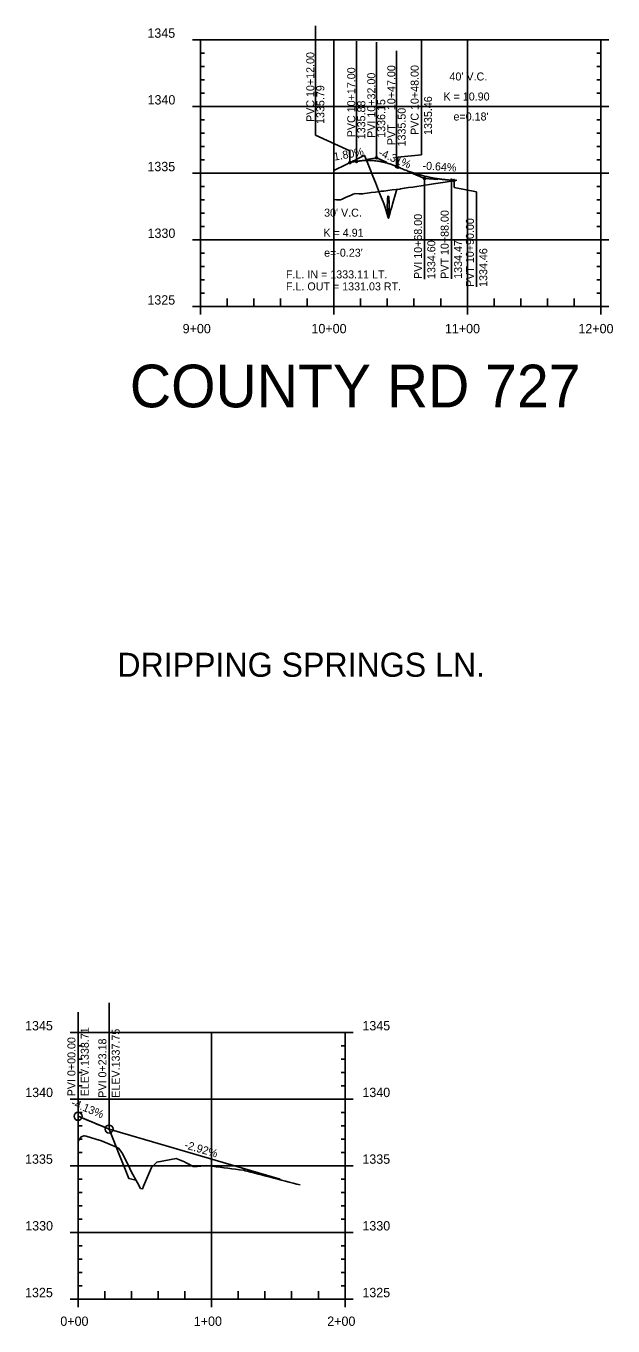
# Model space of a CAD drawing. Extents: x 1371206 to 1374178, y 379328 to 381511.
# Drawn here: x 1372543 to 1372983, y 380536 to 381511 of the extents above; entities that cross this region are included whole.
import ezdxf

# ---------------------------------------------------------------- set-up
doc = ezdxf.new("R2010")
doc.units = 0
for name, color, linetype in [('30', 7, 'Continuous'), ('37', 7, 'Continuous'), ('R_Draft', 7, 'Continuous'), ('R_Drainage', 7, 'Continuous'), ('R_Exist Surface', 7, 'Continuous'), ('R_Fin Surface', 7, 'Continuous'), ('R_Horz Alg Annot', 7, 'Continuous'), ('R_No Plot', 7, 'Continuous'), ('R_Vert Alg', 7, 'Continuous'), ('R_Vert Alg Annot', 7, 'Continuous')]:
    doc.layers.add(name, color=color, linetype=linetype)

msp = doc.modelspace()

# ---------------------------------------------------------------- linework, layer by layer
at = {"layer": '37'}
for p, q in [((1372667.55, 381500.54), (1372673.55, 381500.54)), ((1372667.55, 381500.54), (1372673.55, 381500.54)), ((1372673.55, 381300.54), (1372673.55, 381500.54)), ((1372673.55, 381500.54), (1372973.55, 381500.54)), ((1372673.55, 381500.54), (1372973.55, 381500.54)), ((1372773.55, 381300.54), (1372773.55, 381500.54)), ((1372873.55, 381300.54), (1372873.55, 381500.54)), ((1372973.55, 381300.54), (1372973.55, 381500.54)), ((1372979.55, 381500.54), (1372973.55, 381500.54)), ((1372979.55, 381500.54), (1372973.55, 381500.54)), ((1372673.55, 381490.54), (1372676.55, 381490.54)), ((1372973.55, 381490.54), (1372970.55, 381490.54)), ((1372673.55, 381480.54), (1372676.55, 381480.54)), ((1372973.55, 381480.54), (1372970.55, 381480.54)), ((1372673.55, 381470.54), (1372676.55, 381470.54)), ((1372973.55, 381470.54), (1372970.55, 381470.54)), ((1372673.55, 381460.54), (1372676.55, 381460.54)), ((1372973.55, 381460.54), (1372970.55, 381460.54)), ((1372667.55, 381450.54), (1372673.55, 381450.54)), ((1372673.55, 381450.54), (1372973.55, 381450.54)), ((1372979.55, 381450.54), (1372973.55, 381450.54)), ((1372673.55, 381440.54), (1372676.55, 381440.54)), ((1372973.55, 381440.54), (1372970.55, 381440.54)), ((1372673.55, 381430.54), (1372676.55, 381430.54)), ((1372973.55, 381430.54), (1372970.55, 381430.54)), ((1372673.55, 381420.54), (1372676.55, 381420.54)), ((1372973.55, 381420.54), (1372970.55, 381420.54)), ((1372673.55, 381410.54), (1372676.55, 381410.54)), ((1372973.55, 381410.54), (1372970.55, 381410.54)), ((1372667.55, 381400.54), (1372673.55, 381400.54)), ((1372673.55, 381400.54), (1372973.55, 381400.54)), ((1372979.55, 381400.54), (1372973.55, 381400.54)), ((1372673.55, 381390.54), (1372676.55, 381390.54)), ((1372973.55, 381390.54), (1372970.55, 381390.54)), ((1372673.55, 381380.54), (1372676.55, 381380.54)), ((1372973.55, 381380.54), (1372970.55, 381380.54)), ((1372673.55, 381370.54), (1372676.55, 381370.54)), ((1372973.55, 381370.54), (1372970.55, 381370.54)), ((1372673.55, 381360.54), (1372676.55, 381360.54)), ((1372973.55, 381360.54), (1372970.55, 381360.54)), ((1372667.55, 381350.54), (1372673.55, 381350.54)), ((1372673.55, 381350.54), (1372973.55, 381350.54)), ((1372979.55, 381350.54), (1372973.55, 381350.54)), ((1372673.55, 381340.54), (1372676.55, 381340.54)), ((1372973.55, 381340.54), (1372970.55, 381340.54)), ((1372673.55, 381330.54), (1372676.55, 381330.54)), ((1372973.55, 381330.54), (1372970.55, 381330.54)), ((1372673.55, 381320.54), (1372676.55, 381320.54)), ((1372973.55, 381320.54), (1372970.55, 381320.54)), ((1372673.55, 381310.54), (1372676.55, 381310.54)), ((1372693.55, 381300.54), (1372693.55, 381306.54)), ((1372713.55, 381300.54), (1372713.55, 381306.54)), ((1372733.55, 381300.54), (1372733.55, 381306.54)), ((1372753.55, 381300.54), (1372753.55, 381306.54)), ((1372793.55, 381300.54), (1372793.55, 381306.54)), ((1372813.55, 381300.54), (1372813.55, 381306.54)), ((1372833.55, 381300.54), (1372833.55, 381306.54)), ((1372853.55, 381300.54), (1372853.55, 381306.54)), ((1372893.55, 381300.54), (1372893.55, 381306.54)), ((1372913.55, 381300.54), (1372913.55, 381306.54)), ((1372933.55, 381300.54), (1372933.55, 381306.54)), ((1372953.55, 381300.54), (1372953.55, 381306.54)), ((1372973.55, 381310.54), (1372970.55, 381310.54)), ((1372667.55, 381300.54), (1372673.55, 381300.54)), ((1372673.55, 381300.54), (1372973.55, 381300.54)), ((1372673.55, 381294.54), (1372673.55, 381300.54)), ((1372773.55, 381294.54), (1372773.55, 381300.54)), ((1372873.55, 381294.54), (1372873.55, 381300.54)), ((1372979.55, 381300.54), (1372973.55, 381300.54)), ((1372973.55, 381294.54), (1372973.55, 381300.54)), ((1372575.89, 380756.5), (1372581.89, 380756.5)), ((1372575.89, 380756.5), (1372581.89, 380756.5)), ((1372581.89, 380556.5), (1372581.89, 380756.5)), ((1372581.89, 380756.5), (1372781.89, 380756.5)), ((1372581.89, 380756.5), (1372781.89, 380756.5)), ((1372681.89, 380556.5), (1372681.89, 380756.5)), ((1372781.89, 380556.5), (1372781.89, 380756.5)), ((1372787.89, 380756.5), (1372781.89, 380756.5)), ((1372787.89, 380756.5), (1372781.89, 380756.5)), ((1372581.89, 380746.5), (1372584.89, 380746.5)), ((1372781.89, 380746.5), (1372778.89, 380746.5)), ((1372581.89, 380736.5), (1372584.89, 380736.5)), ((1372781.89, 380736.5), (1372778.89, 380736.5)), ((1372581.89, 380726.5), (1372584.89, 380726.5)), ((1372781.89, 380726.5), (1372778.89, 380726.5)), ((1372581.89, 380716.5), (1372584.89, 380716.5)), ((1372781.89, 380716.5), (1372778.89, 380716.5)), ((1372575.89, 380706.5), (1372581.89, 380706.5)), ((1372581.89, 380706.5), (1372781.89, 380706.5)), ((1372787.89, 380706.5), (1372781.89, 380706.5)), ((1372581.89, 380696.5), (1372584.89, 380696.5)), ((1372781.89, 380696.5), (1372778.89, 380696.5)), ((1372581.89, 380686.5), (1372584.89, 380686.5)), ((1372781.89, 380686.5), (1372778.89, 380686.5)), ((1372581.89, 380676.5), (1372584.89, 380676.5)), ((1372781.89, 380676.5), (1372778.89, 380676.5)), ((1372581.89, 380666.5), (1372584.89, 380666.5)), ((1372781.89, 380666.5), (1372778.89, 380666.5)), ((1372575.89, 380656.5), (1372581.89, 380656.5)), ((1372581.89, 380656.5), (1372781.89, 380656.5)), ((1372787.89, 380656.5), (1372781.89, 380656.5)), ((1372581.89, 380646.5), (1372584.89, 380646.5)), ((1372781.89, 380646.5), (1372778.89, 380646.5)), ((1372581.89, 380636.5), (1372584.89, 380636.5)), ((1372781.89, 380636.5), (1372778.89, 380636.5)), ((1372581.89, 380626.5), (1372584.89, 380626.5)), ((1372781.89, 380626.5), (1372778.89, 380626.5)), ((1372581.89, 380616.5), (1372584.89, 380616.5)), ((1372781.89, 380616.5), (1372778.89, 380616.5)), ((1372575.89, 380606.5), (1372581.89, 380606.5)), ((1372581.89, 380606.5), (1372781.89, 380606.5)), ((1372787.89, 380606.5), (1372781.89, 380606.5)), ((1372581.89, 380596.5), (1372584.89, 380596.5)), ((1372781.89, 380596.5), (1372778.89, 380596.5)), ((1372581.89, 380586.5), (1372584.89, 380586.5)), ((1372781.89, 380586.5), (1372778.89, 380586.5)), ((1372581.89, 380576.5), (1372584.89, 380576.5)), ((1372781.89, 380576.5), (1372778.89, 380576.5)), ((1372581.89, 380566.5), (1372584.89, 380566.5)), ((1372601.89, 380556.5), (1372601.89, 380562.5)), ((1372621.89, 380556.5), (1372621.89, 380562.5)), ((1372641.89, 380556.5), (1372641.89, 380562.5)), ((1372661.89, 380556.5), (1372661.89, 380562.5)), ((1372701.89, 380556.5), (1372701.89, 380562.5)), ((1372721.89, 380556.5), (1372721.89, 380562.5)), ((1372741.89, 380556.5), (1372741.89, 380562.5)), ((1372761.89, 380556.5), (1372761.89, 380562.5)), ((1372781.89, 380566.5), (1372778.89, 380566.5)), ((1372575.89, 380556.5), (1372581.89, 380556.5)), ((1372581.89, 380556.5), (1372781.89, 380556.5)), ((1372581.89, 380550.5), (1372581.89, 380556.5)), ((1372681.89, 380550.5), (1372681.89, 380556.5)), ((1372787.89, 380556.5), (1372781.89, 380556.5)), ((1372781.89, 380550.5), (1372781.89, 380556.5))]:
    msp.add_line(p, q, dxfattribs=at)
at = {"layer": 'R_Drainage'}
msp.add_ellipse((1372814.3, 381376.04), major_axis=(0, 7.5), ratio=0.1, dxfattribs=at)
at = {"layer": 'R_Exist Surface'}
for points in [[(1372773.55, 381380.88), (1372775.54, 381380.49), (1372776.57, 381380.51), (1372778.43, 381380.54), (1372779.69, 381381.1), (1372782.81, 381382.5), (1372785.93, 381383.9), (1372788.11, 381384.89), (1372789.04, 381385.14), (1372789.24, 381385.2), (1372792.16, 381385.17), (1372793.33, 381385.15), (1372793.4, 381385.08), (1372794.77, 381385.14), (1372795.28, 381385.19), (1372796.48, 381385.31), (1372798.4, 381385.57), (1372801.51, 381385.98), (1372804.63, 381386.39), (1372807.75, 381386.79), (1372809.02, 381386.95), (1372809.62, 381387.01), (1372810.87, 381387.17), (1372813.98, 381387.57), (1372817.1, 381387.97), (1372820.22, 381388.35), (1372822.87, 381388.68), (1372823.33, 381388.76), (1372823.76, 381388.84), (1372826.26, 381389.32), (1372826.45, 381389.34), (1372829.57, 381389.73), (1372832.69, 381390.14), (1372835.8, 381390.57), (1372838.92, 381391.01), (1372842.04, 381391.47), (1372842.06, 381391.47), (1372845.16, 381391.95), (1372848.27, 381392.45), (1372856.98, 381393.86), (1372861.3, 381394.67), (1372865.74, 381395.23)], [(1372581.89, 380674.87), (1372584.28, 380678.31), (1372584.89, 380678.43), (1372586.15, 380678.91), (1372586.72, 380678.88), (1372587.94, 380678.59), (1372595.14, 380676.53), (1372599.42, 380675.29), (1372605.96, 380672.4), (1372610.76, 380670.52), (1372612.05, 380669.6), (1372613.2, 380668.52), (1372614.31, 380666.73), (1372615.12, 380665.72), (1372620.53, 380654.5), (1372621.59, 380652.28), (1372626.43, 380643.67), (1372628.67, 380639.58), (1372630.07, 380639.27), (1372630.17, 380639.25), (1372630.94, 380641.16), (1372637, 380655.16), (1372640.76, 380659.11), (1372655.33, 380661.86), (1372661.54, 380659.36), (1372662.43, 380658.9), (1372665.31, 380657.43), (1372668.18, 380656), (1372668.48, 380655.86), (1372671.06, 380656.08), (1372672.42, 380656.21), (1372672.48, 380656.25), (1372672.49, 380656.24), (1372673.94, 380656.33), (1372676.82, 380656.51), (1372678.42, 380656.6), (1372679.7, 380656.45), (1372682.57, 380656.09), (1372685.28, 380655.75), (1372685.45, 380655.73), (1372688.33, 380655.36), (1372691.21, 380655), (1372694.09, 380654.64), (1372696.97, 380654.28), (1372699.84, 380653.92), (1372702.72, 380653.55), (1372705.6, 380653.19), (1372706.13, 380653.13), (1372707.03, 380652.74), (1372707.09, 380652.72), (1372708.48, 380652.36), (1372711.36, 380651.62), (1372714.23, 380650.88), (1372717.11, 380650.14), (1372719.99, 380649.4), (1372722.87, 380648.65), (1372725.75, 380647.9), (1372727.78, 380647.37), (1372728.62, 380647.16), (1372731.5, 380646.46), (1372734.38, 380645.75), (1372737.25, 380645.04), (1372737.26, 380645.04), (1372740.14, 380644.3), (1372743.02, 380643.55), (1372745.89, 380642.8), (1372748.26, 380642.18)]]:
    msp.add_lwpolyline(points, dxfattribs=at)
at = {"layer": 'R_Fin Surface'}
for points in [[(1372773.55, 381402.67), (1372776.57, 381404.12), (1372779.69, 381405.62), (1372782.81, 381407.12), (1372785.55, 381408.45), (1372785.78, 381408.57), (1372785.93, 381408.64), (1372786.34, 381408.84), (1372787.46, 381409.38), (1372787.55, 381409.43), (1372788.27, 381409.78), (1372789.04, 381410.16), (1372792.16, 381411.68), (1372795.28, 381413.21), (1372796.54, 381413.83), (1372798.4, 381409.17), (1372801.44, 381401.5), (1372801.51, 381401.31), (1372804.63, 381393.46), (1372807.75, 381385.59), (1372808.95, 381382.57), (1372810.38, 381378.95), (1372810.87, 381377.73), (1372811.68, 381375.67), (1372812.89, 381371.62), (1372813.98, 381367.98), (1372814.35, 381366.75), (1372815.65, 381371.17), (1372816.18, 381372.99), (1372817.1, 381376.13), (1372817.47, 381377.38), (1372820.22, 381386.78), (1372820.67, 381388.33)], [(1372581.89, 380693.58), (1372581.89, 380693.58), (1372589.41, 380690.47), (1372593.9, 380688.61), (1372594.33, 380688.44), (1372595.91, 380687.78), (1372600.63, 380685.83), (1372605.08, 380683.99), (1372608.07, 380676.51), (1372612.65, 380665.06), (1372617.11, 380653.93), (1372619.93, 380646.87), (1372622.09, 380646.44), (1372625.23, 380645.81)]]:
    msp.add_lwpolyline(points, dxfattribs=at)
at = {"layer": 'R_Vert Alg'}
for p, q in [((1372785.55, 381408.44), (1372790.55, 381409.34)), ((1372798.05, 381410.69), (1372805.55, 381412.04)), ((1372805.55, 381412.04), (1372813.05, 381408.81)), ((1372820.55, 381405.58), (1372821.55, 381405.15)), ((1372831.55, 381400.84), (1372841.55, 381396.54)), ((1372841.55, 381396.54), (1372851.55, 381395.9)), ((1372861.55, 381395.26), (1372863.55, 381395.14)), ((1372581.89, 380693.58), (1372605.08, 380683.99)), ((1372605.08, 380683.99), (1372733.26, 380646.56))]:
    msp.add_line(p, q, dxfattribs=at)
for points in [[(1372790.55, 381409.34), (1372791.17, 381409.44), (1372791.8, 381409.55), (1372792.42, 381409.64), (1372793.05, 381409.72), (1372793.67, 381409.8), (1372794.3, 381409.87), (1372794.92, 381409.93), (1372795.55, 381409.98), (1372796.17, 381410.03), (1372796.8, 381410.06), (1372797.42, 381410.09), (1372798.05, 381410.11), (1372798.67, 381410.13), (1372799.3, 381410.13), (1372799.92, 381410.13), (1372800.55, 381410.12), (1372801.17, 381410.1), (1372801.8, 381410.07), (1372802.42, 381410.04), (1372803.05, 381410), (1372803.67, 381409.95), (1372804.3, 381409.89), (1372804.92, 381409.82), (1372806.17, 381409.66), (1372806.8, 381409.57), (1372807.42, 381409.48), (1372808.05, 381409.37), (1372808.67, 381409.26), (1372809.3, 381409.13), (1372809.92, 381409), (1372810.55, 381408.87), (1372811.17, 381408.72), (1372811.8, 381408.57), (1372812.42, 381408.4), (1372813.05, 381408.23), (1372813.67, 381408.06), (1372814.3, 381407.87), (1372814.92, 381407.68), (1372815.55, 381407.48), (1372816.17, 381407.27), (1372816.8, 381407.05), (1372817.42, 381406.82), (1372818.05, 381406.59), (1372818.67, 381406.35), (1372819.3, 381406.1), (1372819.92, 381405.84), (1372820.55, 381405.58)], [(1372821.55, 381405.15), (1372822.38, 381404.79), (1372823.21, 381404.44), (1372824.05, 381404.1), (1372824.88, 381403.76), (1372825.71, 381403.43), (1372826.55, 381403.11), (1372827.38, 381402.79), (1372828.21, 381402.48), (1372829.05, 381402.18), (1372829.88, 381401.88), (1372830.71, 381401.59), (1372831.55, 381401.3), (1372832.38, 381401.02), (1372833.21, 381400.75), (1372834.05, 381400.48), (1372834.88, 381400.22), (1372835.71, 381399.97), (1372836.55, 381399.72), (1372837.38, 381399.48), (1372838.21, 381399.25), (1372839.05, 381399.02), (1372839.88, 381398.8), (1372840.71, 381398.58), (1372842.38, 381398.17), (1372843.21, 381397.97), (1372844.05, 381397.78), (1372844.88, 381397.6), (1372845.71, 381397.42), (1372846.55, 381397.25), (1372847.38, 381397.09), (1372848.21, 381396.93), (1372849.05, 381396.78), (1372849.88, 381396.63), (1372850.71, 381396.49), (1372851.55, 381396.36), (1372852.38, 381396.23), (1372853.21, 381396.11), (1372854.05, 381396), (1372854.88, 381395.89), (1372855.71, 381395.79), (1372856.55, 381395.7), (1372857.38, 381395.61), (1372858.21, 381395.53), (1372859.05, 381395.45), (1372859.88, 381395.38), (1372860.71, 381395.32), (1372861.55, 381395.26)]]:
    msp.add_lwpolyline(points, dxfattribs=at)
for centre, radius in [((1372785.55, 381408.44), 0.75), ((1372790.55, 381409.34), 0.75), ((1372805.55, 381412.04), 0.75), ((1372820.55, 381405.58), 0.75), ((1372821.55, 381405.15), 0.75), ((1372841.55, 381396.54), 0.75), ((1372861.55, 381395.26), 0.75), ((1372863.55, 381395.14), 0.75), ((1372581.89, 380693.58), 3), ((1372605.08, 380683.99), 3)]:
    msp.add_circle(centre, radius, dxfattribs=at)
at = {"layer": 'R_Vert Alg Annot'}
for p, q in [((1372759.75, 381428.98), (1372759.75, 381510.88)), ((1372790.55, 381409.34), (1372790.55, 381499.4)), ((1372805.55, 381412.04), (1372805.55, 381498.78)), ((1372839.07, 381414.19), (1372839.07, 381500.94)), ((1372820.55, 381405.58), (1372820.55, 381492.33)), ((1372759.75, 381428.98), (1372785.55, 381417.28)), ((1372785.55, 381408.45), (1372785.55, 381417.28)), ((1372839.07, 381414.19), (1372821.55, 381412.48)), ((1372821.55, 381405.15), (1372821.55, 381412.48)), ((1372841.55, 381396.54), (1372841.55, 381321.22)), ((1372861.55, 381395.26), (1372861.55, 381321.35)), ((1372863.55, 381395.14), (1372863.55, 381389.93)), ((1372863.55, 381389.93), (1372880.44, 381386.64)), ((1372880.44, 381386.64), (1372880.44, 381315.29)), ((1372605.08, 380683.99), (1372605.08, 380778.73)), ((1372581.89, 380693.58), (1372581.89, 380771.58))]:
    msp.add_line(p, q, dxfattribs=at)

# ---------------------------------------------------------------- texts
at = {"layer": '30'}
for s, p in [('1345', (1372633.81, 381502.04)), ('1345', (1372633.81, 381502.04)), ('1340', (1372633.93, 381452.04)), ('1335', (1372633.81, 381402.04)), ('1330', (1372633.93, 381352.04)), ('1325', (1372633.81, 381302.04)), ('9+00', (1372660.24, 381280.54)), ('10+00', (1372756.74, 381280.54)), ('11+00', (1372856.74, 381280.54)), ('12+00', (1372956.74, 381280.54)), ('1345', (1372542.15, 380758)), ('1345', (1372542.15, 380758)), ('1345', (1372794.89, 380758)), ('1345', (1372794.89, 380758)), ('1340', (1372542.28, 380708)), ('1340', (1372794.89, 380708)), ('1335', (1372542.15, 380658)), ('1335', (1372794.89, 380658)), ('1330', (1372542.28, 380608)), ('1330', (1372794.89, 380608)), ('1325', (1372542.15, 380558)), ('1325', (1372794.89, 380558)), ('0+00', (1372568.58, 380536.5)), ('1+00', (1372668.58, 380536.5)), ('2+00', (1372768.58, 380536.5))]:
    msp.add_text(s, height=7, dxfattribs=at).set_placement(p)
at = {"layer": 'R_Draft'}
for s, p in [('F.L. IN = 1333.11 LT.', (1372737.63, 381321.68)), ('F.L. OUT = 1331.03 RT.', (1372737.63, 381312.68))]:
    msp.add_text(s, height=6, dxfattribs=at).set_placement(p)
at = {"layer": 'R_Horz Alg Annot'}
msp.add_text('DRIPPING SPRINGS LN.', height=18, dxfattribs=at).set_placement((1372611.29, 381023.06))
at = {"layer": 'R_No Plot'}
msp.add_text('COUNTY RD 727', height=32, dxfattribs=at).set_placement((1372620.66, 381225.02))
at = {"layer": 'R_Vert Alg Annot'}
for s, rotation, p in [('PVC 10+12.00', 90, (1372758.88, 381438.94)), ('PVC 10+17.00', 90, (1372789.57, 381427.46)), (' 10+47.00', 90, (1372819.56, 381445.59)), ('PVC 10+48.00', 90, (1372837.07, 381429.19)), ('PVI 10+32.00', 90, (1372804.58, 381427.04)), ('1335.79', 90, (1372766.39, 381437.45)), ('1335.46', 90, (1372847.07, 381429.19)), ('1335.88', 90, (1372797.06, 381425.97)), ('1336.15', 90, (1372812.04, 381427.04)), ('1335.50', 90, (1372827.32, 381420.58)), ('PVT', 90, (1372819.56, 381421.59)), ('1.80%', 10.20397, (1372773.91, 381409.91)), ('-4.31%', 336.70544, (1372806.41, 381413.84)), ('-0.64%', 356.35881, (1372839.8, 381403.34)), ('PVI 10+68.00', 90, (1372839.55, 381321.22)), ('PVT 10+88.00', 90, (1372859.55, 381321.35)), ('PVT 10+90.00', 90, (1372878.44, 381315.29)), ('1334.60', 90, (1372849.55, 381321.22)), ('1334.47', 90, (1372869.55, 381321.35)), ('1334.46', 90, (1372888.44, 381315.29)), ('ELEV.1338.71', 90, (1372589.89, 380708.58)), ('ELEV.1337.75', 90, (1372613.08, 380707.5)), ('PVI 0+00.00', 90, (1372579.89, 380708.58)), ('PVI 0+23.18', 90, (1372603.08, 380707.5)), ('-4.13%', 337.53708, (1372576.13, 380701.58)), ('-2.92%', 343.72023, (1372661.1, 380669.72))]:
    msp.add_text(s, height=6, rotation=rotation, dxfattribs=at).set_placement(p)
for s, p in [("40' V.C.", (1372860.15, 381470.03)), ('K = 10.90', (1372855.64, 381455.03)), ("e=0.18'", (1372863.15, 381440.03)), ("30' V.C.", (1372766.21, 381367.93)), ('K = 4.91', (1372765.7, 381352.93)), ("e=-0.23'", (1372766.21, 381337.93))]:
    msp.add_text(s, height=6, dxfattribs=at).set_placement(p)

doc.saveas('drawing.dxf')
